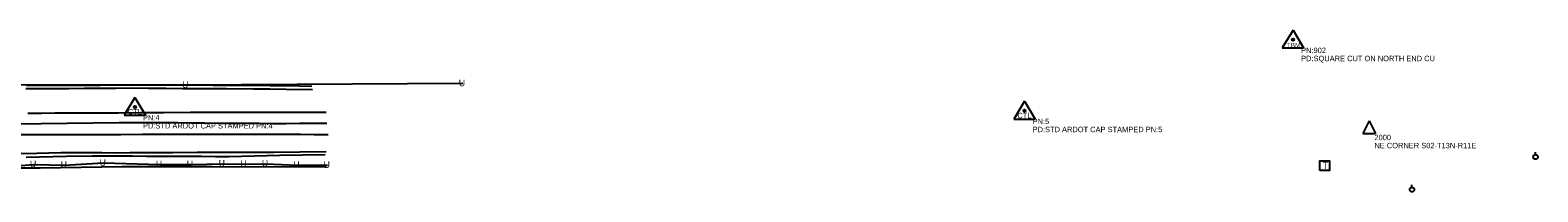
# Model space of a CAD drawing. Extents: x 1939239 to 1943096, y 531224 to 537447.
# Drawn here: x 1941700 to 1943096, y 534740 to 534890 of the extents above; entities that cross this region are included whole.
import ezdxf

# ---------------------------------------------------------------- set-up
doc = ezdxf.new("R2010")
doc.units = 0
for name, color, linetype in [('Default', 7, 'Continuous'), ('S_BASELINE', 7, 'Continuous'), ('S_CAL_CORNER', 7, 'Continuous'), ('S_CAL_CORNER_ANNOT', 7, 'Continuous'), ('S_DITCHLINE', 7, 'Continuous'), ('S_EDGE_PAVEMENT', 7, 'Continuous'), ('S_PAVEMENT_CROWN', 7, 'Continuous'), ('S_PRIMARY_CTL', 7, 'Continuous'), ('S_PRIMARY_CTL_ANNOT', 7, 'Continuous'), ('S_TELEPHONE_UTILITIES', 7, 'Continuous'), ('S_UNDERGROUND_CABLE', 7, 'Continuous'), ('S_UTILITY_POLE', 7, 'Continuous'), ('S_UTL_PT_SYM', 7, 'Continuous'), ('S_WATER_UTILITIES', 7, 'Continuous')]:
    doc.layers.add(name, color=color, linetype=linetype)

msp = doc.modelspace()

# ---------------------------------------------------------------- linework, layer by layer
at = {"layer": 'S_BASELINE'}
msp.add_line((1942620.7, 534815.5), (1942620.7, 534815.5), dxfattribs=at)
at = {"layer": 'S_CAL_CORNER'}
for p, q in [((1942939.8, 534806.1), (1942933.9, 534794.3)), ((1942939.8, 534806.1), (1942945.6, 534794.3)), ((1942933.9, 534794.3), (1942945.6, 534794.3))]:
    msp.add_line(p, q, dxfattribs=at)
at = {"layer": 'S_DITCHLINE'}
for points in [[(1941961.3, 534834.8), (1941937.2, 534835.1), (1941922, 534835.3), (1941906.8, 534835.4), (1941881.9, 534835.5), (1941857, 534835.6), (1941841.2, 534835.7), (1941825.5, 534835.9), (1941809.7, 534836), (1941793.9, 534836.1), (1941779.4, 534836), (1941764.8, 534835.9), (1941750.3, 534835.8), (1941735.8, 534835.7), (1941722.5, 534835.6), (1941709.3, 534835.6), (1941696, 534835.6)], [(1941960.9, 534837.8), (1941937.5, 534838.5), (1941922.4, 534838.5), (1941907.4, 534838.6), (1941894.7, 534838.6), (1941882.1, 534838.7), (1941869.5, 534838.8), (1941856.9, 534838.9), (1941841.1, 534838.9), (1941825.2, 534838.9), (1941809.3, 534838.9), (1941793.4, 534838.9), (1941779.1, 534838.9), (1941764.8, 534838.8), (1941750.5, 534838.8), (1941736.1, 534838.7), (1941722.9, 534838.7), (1941709.7, 534838.7), (1941696.5, 534838.7)], [(1941974.1, 534777.4), (1941949.7, 534777.1), (1941925.3, 534776.7), (1941901.2, 534776.7), (1941877, 534776.7), (1941854.6, 534776.6), (1941832.2, 534776.5), (1941818.9, 534776.5), (1941805.7, 534776.4), (1941792.4, 534776.3), (1941779.1, 534776.2), (1941766.5, 534776.3), (1941753.8, 534776.4), (1941741.2, 534776.5), (1941728.5, 534776.5), (1941706.2, 534775.9), (1941684, 534775.3)], [(1941696.2, 534772.4), (1941708.7, 534772.7), (1941721.3, 534773.1), (1941733.8, 534773.4), (1941757.7, 534773.5), (1941781.6, 534773.5), (1941794.7, 534773.5), (1941807.8, 534773.4), (1941821, 534773.4), (1941834.1, 534773.4), (1941846.6, 534773.3), (1941859.1, 534773.2), (1941871.6, 534773.1), (1941884.1, 534773), (1941907.6, 534773.5), (1941931.2, 534774.1), (1941952.2, 534774.4), (1941973.2, 534774.8)]]:
    msp.add_lwpolyline(points, dxfattribs=at)
at = {"layer": 'S_EDGE_PAVEMENT'}
for points in [[(1941697.9, 534813.1), (1941710.4, 534813.2), (1941723, 534813.3), (1941735.5, 534813.4), (1941758.5, 534813.5), (1941781.5, 534813.5), (1941802.5, 534813.7), (1941823.5, 534813.8), (1941848.4, 534814), (1941873.3, 534814.1), (1941886.1, 534814.1), (1941898.9, 534814.1), (1941911.7, 534814), (1941924.6, 534814), (1941949.4, 534813.9), (1941974.2, 534813.9)], [(1941687.1, 534793.4), (1941710.1, 534793.3), (1941733, 534793.2), (1941745.7, 534793.2), (1941758.4, 534793.3), (1941771.2, 534793.4), (1941783.9, 534793.4), (1941804.1, 534793.6), (1941824.4, 534793.8), (1941837.4, 534793.8), (1941850.3, 534793.7), (1941863.2, 534793.7), (1941876.2, 534793.6), (1941900.6, 534793.6), (1941924.9, 534793.7), (1941937.7, 534793.6), (1941950.4, 534793.5), (1941963.1, 534793.4), (1941975.9, 534793.3)]]:
    msp.add_lwpolyline(points, dxfattribs=at)
at = {"layer": 'S_PAVEMENT_CROWN'}
msp.add_lwpolyline([(1941686.2, 534803.3), (1941710.2, 534803.5), (1941734.2, 534803.8), (1941758.3, 534804), (1941782.4, 534804.3), (1941803.1, 534804.4), (1941823.7, 534804.5), (1941836.3, 534804.4), (1941849, 534804.2), (1941861.6, 534804), (1941874.2, 534803.9), (1941886.8, 534803.8), (1941899.4, 534803.7), (1941912, 534803.7), (1941924.7, 534803.6), (1941937.2, 534803.6), (1941949.7, 534803.7), (1941962.3, 534803.8), (1941974.8, 534803.8)], dxfattribs=at)
at = {"layer": 'S_PRIMARY_CTL'}
for p, q in [((1942869.3, 534889.9), (1942859.3, 534873.4)), ((1942869.3, 534889.9), (1942879.1, 534873.4)), ((1942859.3, 534873.4), (1942879.1, 534873.4)), ((1941797, 534827.6), (1941787, 534811.1)), ((1941797, 534827.6), (1941806.9, 534811.1)), ((1942620.7, 534824.2), (1942610.7, 534807.6)), ((1942620.7, 534824.2), (1942630.6, 534807.6)), ((1941787, 534811.1), (1941806.9, 534811.1)), ((1942610.7, 534807.6), (1942630.6, 534807.6))]:
    msp.add_line(p, q, dxfattribs=at)
for centre, radius in [((1942869.3, 534881.2), 1.04), ((1942869.3, 534881.2), 0.609), ((1942869.3, 534881.2), 0.344), ((1941797, 534818.9), 1.04), ((1941797, 534818.9), 0.609), ((1941797, 534818.9), 0.344), ((1942620.7, 534815.5), 1.04), ((1942620.7, 534815.5), 0.609), ((1942620.7, 534815.5), 0.344)]:
    msp.add_circle(centre, radius, dxfattribs=at)
at = {"layer": 'S_TELEPHONE_UTILITIES'}
msp.add_lwpolyline([(1942894.2, 534760), (1942894.2, 534769), (1942903.2, 534769), (1942903.2, 534760)], close=True, dxfattribs=at)
at = {"layer": 'S_UNDERGROUND_CABLE'}
for p, q in [((1941844.5, 534839.1), (1941595, 534839.2)), ((1942100.6, 534840.6), (1941844.5, 534839.1)), ((1941683.7, 534764), (1941703.4, 534765.6)), ((1941703.4, 534765.6), (1941731.9, 534765.1)), ((1941731.9, 534765.1), (1941768, 534767)), ((1941768, 534767), (1941820, 534765.6)), ((1941820, 534765.6), (1941848.7, 534765.7)), ((1941848.7, 534765.7), (1941878.3, 534766.1)), ((1941878.3, 534766.1), (1941898.4, 534766)), ((1941898.4, 534766), (1941918.2, 534766.3)), ((1941918.2, 534766.3), (1941947.3, 534765.1)), ((1941947.3, 534765.1), (1941975.4, 534765))]:
    msp.add_line(p, q, dxfattribs=at)
at = {"layer": 'S_UTILITY_POLE'}
for p, q in [((1943093.8, 534774.7), (1943093.8, 534776.9)), ((1942979.4, 534744.6), (1942979.4, 534746.7))]:
    msp.add_line(p, q, dxfattribs=at)
for centre in [(1943093.9, 534772.6), (1942979.5, 534742.4)]:
    msp.add_circle(centre, 2.13, dxfattribs=at)
at = {"layer": 'S_UTL_PT_SYM'}
for points in [[(1941709, 534762.2), (1941709, 534762.2), (1941709, 534762.2), (1941708.9, 534762.2), (1941709, 534762.2), (1941709, 534762.1), (1941709, 534762.2), (1941709, 534762.2)], [(1941785.6, 534763.5), (1941785.6, 534763.6), (1941785.6, 534763.5), (1941785.5, 534763.5), (1941785.6, 534763.5), (1941785.6, 534763.5), (1941785.6, 534763.5), (1941785.6, 534763.5)], [(1941868.6, 534763.5), (1941868.6, 534763.5), (1941868.6, 534763.5), (1941868.6, 534763.5), (1941868.6, 534763.5), (1941868.6, 534763.4), (1941868.6, 534763.5), (1941868.7, 534763.5)], [(1941973.6, 534763.2), (1941973.6, 534763.2), (1941973.6, 534763.2), (1941973.5, 534763.2), (1941973.6, 534763.2), (1941973.6, 534763.1), (1941973.6, 534763.2), (1941973.6, 534763.2)]]:
    msp.add_lwpolyline(points, dxfattribs=at)
at = {"layer": 'S_WATER_UTILITIES'}
for p, q in [((1941709, 534762.2), (1941630.8, 534762.1)), ((1941785.6, 534763.5), (1941709, 534762.2)), ((1941868.6, 534763.5), (1941785.6, 534763.5)), ((1941973.6, 534763.2), (1941868.6, 534763.5))]:
    msp.add_line(p, q, dxfattribs=at)

# ---------------------------------------------------------------- texts
at = {"layer": 'Default'}
for p in [(1941840.8, 534836.5), (1942096.9, 534838), (1941699.8, 534763.1), (1941728.3, 534762.6), (1941764.4, 534764.4), (1941816.4, 534763.1), (1941845, 534763.2), (1941874.6, 534763.6), (1941894.8, 534763.4), (1941914.6, 534763.7), (1941943.7, 534762.6), (1941971.8, 534762.5)]:
    msp.add_text('U', height=6, dxfattribs=at).set_placement(p)
at = {"layer": 'S_CAL_CORNER_ANNOT'}
for s, p in [('2000', (1942944.7, 534788.1)), ('NE CORNER S02-T13N-R11E', (1942944.7, 534780.6))]:
    msp.add_text(s, height=5, dxfattribs=at).set_placement(p)
at = {"layer": 'S_PRIMARY_CTL'}
for s, height, p in [('TBM', 4.29, (1942863.6, 534873.8)), ('CTL', 5, (1941790.5, 534811.9)), ('CTL', 5, (1942614.1, 534808.4))]:
    msp.add_text(s, height=height, dxfattribs=at).set_placement(p)
at = {"layer": 'S_PRIMARY_CTL_ANNOT'}
for s, p in [('PN:902', (1942876.8, 534868.7)), ('PD:SQUARE CUT ON NORTH END CU', (1942876.8, 534861.2)), ('PN:4', (1941804.5, 534806.4)), ('PD:STD ARDOT CAP STAMPED PN:4', (1941804.5, 534798.9)), ('PN:5', (1942628.2, 534803)), ('PD:STD ARDOT CAP STAMPED PN:5', (1942628.2, 534795.5))]:
    msp.add_text(s, height=5, dxfattribs=at).set_placement(p)
at = {"layer": 'S_TELEPHONE_UTILITIES'}
msp.add_text('T', height=6, dxfattribs=at).set_placement((1942896.8, 534761.5))

doc.saveas('drawing.dxf')
